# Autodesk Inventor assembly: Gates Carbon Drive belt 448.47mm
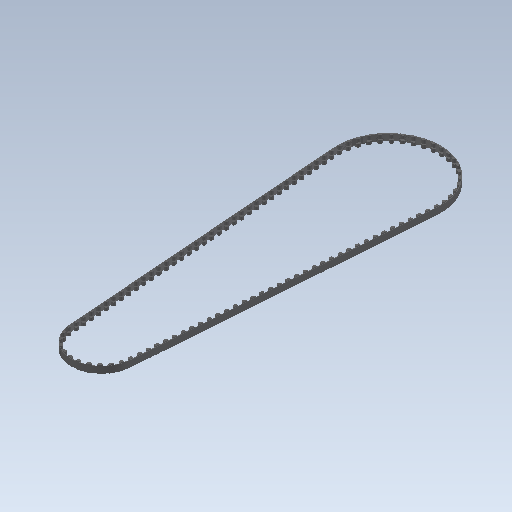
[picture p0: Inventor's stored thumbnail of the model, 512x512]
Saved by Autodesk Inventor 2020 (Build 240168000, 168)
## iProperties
Created: 2017-11
Part Number: Gates Carbon Drive belt 448.47mm
Material: Ogólny
Document SubType Name: Assembly
Designer: Tomasz
Sending System: SolidWorks 2017
Last Author: Tomasz
Last Saved: 2017-11-19
Author: Tomasz
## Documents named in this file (2)
- C:\Users\bruno\Documents\1-Cours-2020-21\1STI2D-2020-21\IT\6. Antivol\Inventor-Antivol\INVENTOR 2018_Steel Hardtail B+\Gates Carbon Drive belt 448.47mm.iam
- C:\Users\bruno\Documents\1-Cours-2020-21\1STI2D-2020-21\IT\6. Antivol\Inventor-Antivol\INVENTOR 2018_Steel Hardtail B+\pasek.iam
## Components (1 placed, 1 different names)
1. pasek:1 [sub-assembly]
